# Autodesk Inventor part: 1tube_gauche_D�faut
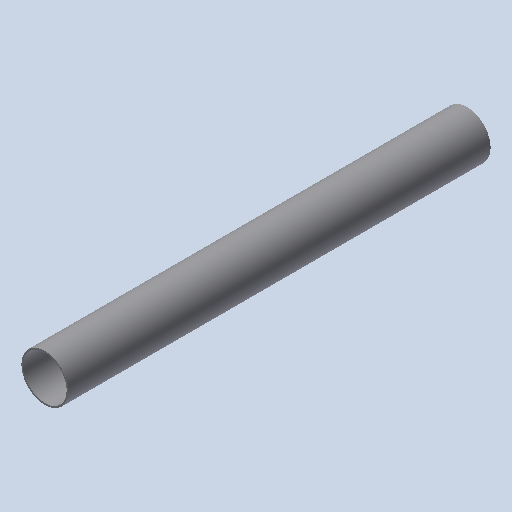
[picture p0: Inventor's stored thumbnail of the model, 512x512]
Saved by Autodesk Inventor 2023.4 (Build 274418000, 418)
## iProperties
Created: 2011-01
Part Number: 1tube_gauche_D�faut
Document SubType Name: Modeling
Designer: eric
Density: 1 g/cm^3
Mass: 24.5987 g
Surface Area: 493.796 cm^2
Volume: 24.5987 cm^3
Material: Générique
Appearance: Par défaut
Author: eric
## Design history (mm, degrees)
feature "Base1"
node "Corps solides"
node "Corps surfaciques"
node "Solide1"
